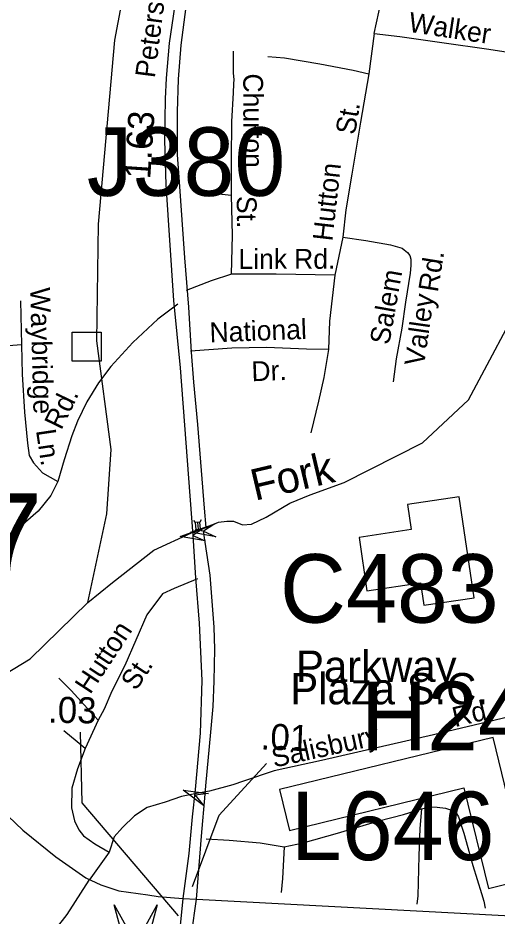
# Model space of a CAD drawing. Extents: x 1547597 to 1699558, y 810033 to 920809.
# Drawn here: x 1627311 to 1629607, y 845229 to 849529 of the extents above; entities that cross this region are included whole.
import ezdxf

# ---------------------------------------------------------------- set-up
doc = ezdxf.new("R2010")
doc.units = 0
for name, color, linetype in [('Exist Cultural Shopping Center Building Footprint', 7, 'Continuous'), ('Exist Cultural Shopping Center Building Label', 7, 'Continuous'), ('Exist Hydrographic Creek Single Shore', 7, 'Continuous'), ('Exist Hydrographic Creek Single Shore Label', 7, 'Continuous'), ('Exist Road Non-System Structure Non-Sys Other CELL', 7, 'Continuous'), ('Exist Road Non-System Structure Non-Sys Other Number Label', 7, 'Continuous'), ('Exist Road Non-System Type 51', 7, 'Continuous'), ('Exist Road Non-System Type 51 Label', 7, 'Continuous'), ('Exist Road Primary Interstate Structure Cantilever Sign Number Label', 7, 'Continuous'), ('Exist Road Primary Interstate Structure Standard Bridge CELL', 7, 'Continuous'), ('Exist Road Primary NC Service Mileage Hundredths English Label', 7, 'Continuous'), ('Exist Road Primary NC UnDivided 4 Lane Attributed', 7, 'Continuous'), ('Exist Road Primary US Structure Non-Sys NCDOT Attributed CELL', 7, 'Continuous'), ('Exist Road Primary US Structure Non-Sys NCDOT Number Label', 7, 'Continuous'), ('Exist Road Secondary Structure Culvert Attributed CELL', 7, 'Continuous'), ('Exist Road Secondary Structure Culvert Number Label', 7, 'Continuous'), ('Exist Road Secondary Structure Standard Bridge Attributed CELL', 7, 'Continuous'), ('Exist Road Secondary Structure Standard Bridge Number Label', 7, 'Continuous'), ('Exist Road Secondary Type 51 Undivided 4 Lane Attributed', 7, 'Continuous')]:
    doc.layers.add(name, color=color, linetype=linetype)

msp = doc.modelspace()

# ---------------------------------------------------------------- linework, layer by layer
at = {"layer": 'Exist Cultural Shopping Center Building Footprint'}
for points in [[(1629497.8, 846753.5), (1629426.1, 847236.8), (1629178.5, 847200.1), (1629196.4, 847079.4), (1628945.9, 847042.3), (1628983.8, 846786.6), (1629241.3, 846824.8), (1629257.2, 846717.8)], [(1629588.2, 846084.1), (1628565.6, 845834.9), (1628613.3, 845639.1), (1629448.5, 845842.7), (1629565.9, 845361.1), (1629753.3, 845406.8)]]:
    msp.add_lwpolyline(points, close=True, dxfattribs=at)
at = {"layer": 'Exist Hydrographic Creek Single Shore'}
for points in [[(1627645.6, 846730.9), (1627737.8, 847155.4), (1627757.8, 847463.5), (1627689.8, 847983.6), (1627697.8, 848541.5), (1627775.8, 849423), (1627945.8, 850322.2)], [(1627645.6, 846730.9), (1627765.1, 846826.2), (1627962.3, 846981.9), (1628143.4, 847063.5), (1628213.2, 847090.1), (1628273, 847114.5), (1628312.9, 847120.6), (1628344.5, 847119.5), (1628388.2, 847102.3), (1628430.9, 847106.2), (1628500.6, 847139.4), (1628614.7, 847207), (1628711.1, 847245.7), (1628875.3, 847305.9), (1629250.8, 847495.6), (1629469.9, 847701.3), (1629752.8, 848230.6), (1629887.9, 848362.4), (1630139.9, 848498.5), (1630507.4, 848857.5), (1630701.1, 849097)], [(1626579.8, 845980.8), (1626862.2, 846153.4), (1626909, 846181.6), (1627369.8, 846460.4), (1627645.6, 846730.9)]]:
    msp.add_lwpolyline(points, dxfattribs=at)
at = {"layer": 'Exist Road Non-System Structure Non-Sys Other CELL'}
msp.add_lwpolyline([(1627571.9, 848025.2), (1627710.9, 848025.2), (1627710.9, 847886.1), (1627571.9, 847886.1)], close=True, dxfattribs=at)
at = {"layer": 'Exist Road Non-System Type 51'}
for p, q in [((1629019, 849455.1), (1628992.3, 849261.9)), ((1628334.3, 848678.5), (1628257.6, 848687.6)), ((1628868, 848479.4), (1628830.3, 848298)), ((1627323.1, 848174.2), (1627327.9, 847964.2)), ((1627696.1, 846167.7), (1627632.7, 846031.3)), ((1627748.4, 845535.3), (1627652.5, 845401.8))]:
    msp.add_line(p, q, dxfattribs=at)
for points in [[(1629019, 849455.1), (1629051.7, 849608.8), (1629069.3, 849744.8), (1629094.5, 849933.8), (1629122.1, 850149.2), (1629144.7, 850300.3), (1629174.9, 850373.4), (1629227.8, 850489.3), (1629343.6, 850781.6), (1629449.5, 851019.3)], [(1629019, 849455.1), (1629140.9, 849440.6), (1629342.2, 849411.7), (1629567.8, 849379.5), (1629784.3, 849346.7), (1629906, 849323.1), (1629962.1, 849316.8), (1630000.9, 849311.4), (1630067.5, 849334), (1630162.6, 849414.5)], [(1628334.3, 848678.5), (1628334.3, 848852.3), (1628336.8, 849033.8), (1628344.9, 849170.1), (1628345.3, 849213.2), (1628347.1, 849234.7), (1628344.4, 849264.6), (1628343.6, 849370.9)], [(1628508.4, 849344.5), (1628588.7, 849337.8), (1628758.9, 849310.2), (1628918.3, 849280.1), (1628992.3, 849261.9)], [(1628992.3, 849261.9), (1628953.6, 849030.3), (1628910.8, 848780.9), (1628883.1, 848610.5), (1628868, 848479.4)], [(1628334.3, 848303.1), (1628339.3, 848489.5), (1628334.3, 848678.5)], [(1628868, 848479.4), (1628978.8, 848464.3), (1629097.2, 848442.9), (1629152.6, 848427.8), (1629163.1, 848418.4), (1629177.6, 848406.9), (1629189.3, 848392.3), (1629193.8, 848373.8), (1629194.8, 848343.8), (1629190.8, 848307.8), (1629168.6, 848168.4), (1629150.9, 848044.7), (1629124.5, 847897.1), (1629108.8, 847787.6)], [(1628334.3, 848303.1), (1628237.2, 848270.1), (1628117.2, 848223.9)], [(1628830.3, 848298), (1628548.3, 848303.1), (1628334.3, 848303.1)], [(1628830.3, 848298), (1628805.2, 848077.5), (1628799.6, 847942)], [(1628077.1, 848159.6), (1627981.1, 848086.4), (1627861.6, 847976.2), (1627755.8, 847859.9), (1627696.8, 847782.8), (1627641.3, 847691.7), (1627596, 847598.4), (1627569, 847528.9), (1627533.2, 847413.5), (1627501.7, 847310.1)], [(1627327.9, 847964.2), (1627181.8, 847952.4), (1627045.9, 847954.5)], [(1627327.9, 847964.2), (1627331.6, 847824.3), (1627342.9, 847642.1), (1627356.8, 847494.2), (1627365.7, 847433.9), (1627385.3, 847399.7), (1627428.5, 847351), (1627501.7, 847310.1)], [(1628799.6, 847942), (1628693.8, 847943.7), (1628503.1, 847951.6), (1628336.9, 847949.1), (1628138, 847933.9)], [(1628799.6, 847942), (1628777.5, 847808), (1628752.3, 847694.6), (1628714.5, 847543.4)], [(1627501.7, 847310.1), (1627468.7, 847242.5), (1627407.6, 847167.5), (1627310.4, 847083.1), (1627189.4, 847006.9), (1627018.3, 846917.5), (1626853.3, 846842), (1626774.9, 846817.2), (1626696.5, 846790.4), (1626620.3, 846773.5), (1626533, 846759.7), (1626404, 846746.9)], [(1628172.2, 846844.6), (1628060.6, 846798.3), (1628004.2, 846772.5), (1627928.9, 846671.3), (1627823.1, 846428.9), (1627762, 846306.6), (1627724.4, 846219.5), (1627696.1, 846167.7)], [(1627507.4, 846368.5), (1627566.4, 846309.6), (1627660.8, 846206.3), (1627696.1, 846167.7)], [(1629997.5, 846262.9), (1629942, 846253.7), (1629857.6, 846229.4), (1629632.2, 846175), (1629302.1, 846096.3), (1629037.5, 846036.2), (1628766.2, 845974.6), (1628539.7, 845923.9), (1628392.4, 845874.8), (1628341.5, 845857.5), (1628228.9, 845826.6), (1628166.9, 845815.5), (1628095.4, 845801.3), (1628017.4, 845775.3), (1627930.5, 845749.8), (1627870, 845708.6), (1627811.9, 845652.9), (1627772.9, 845608.7), (1627748.4, 845535.3)], [(1627632.7, 846031.3), (1627594.7, 846063.3), (1627531.5, 846116.2)], [(1627632.7, 846031.3), (1627597.4, 845934.8), (1627570, 845841.5), (1627567.4, 845747.7), (1627583, 845685.8), (1627603.4, 845642.3), (1627625.8, 845613.3), (1627679.2, 845574.4), (1627748.4, 845535.3)], [(1629245.7, 845742.9), (1629285.7, 845752.3), (1629320.1, 845751), (1629360.4, 845746.2), (1629393.4, 845734.7), (1629404.2, 845728.1), (1629413.1, 845720.5), (1629422.8, 845703.7), (1629447.6, 845625.9), (1629491.1, 845471.4), (1629533, 845336.8), (1629544.5, 845300.8), (1629550.3, 845267.6)], [(1628587.4, 845560.9), (1628677.6, 845579.5), (1628842.3, 845627), (1629041, 845686), (1629159.3, 845716.2), (1629245.7, 845742.9)], [(1629245.7, 845742.9), (1629238.1, 845649), (1629232.1, 845517.2), (1629227.2, 845325.4), (1629223.2, 845286.5)], [(1628213, 845599.3), (1628324.3, 845592.9), (1628472, 845580.7), (1628587.4, 845560.9)], [(1628587.4, 845560.9), (1628579.1, 845409), (1628572.4, 845342.1)], [(1627442.1, 845100.9), (1627455.7, 845120.2), (1627547.3, 845236.8), (1627652.5, 845401.8)]]:
    msp.add_lwpolyline(points, dxfattribs=at)
at = {"layer": 'Exist Road Primary Interstate Structure Standard Bridge CELL'}
for p, q in [((1628190.2, 847126.5), (1628183.4, 847115.2)), ((1628152.8, 847123.5), (1628161.3, 847113.4)), ((1628172.4, 847114.3), (1628175, 847081.1)), ((1628186, 847082), (1628194.5, 847071.9)), ((1628164.2, 847080.3), (1628157.4, 847069))]:
    msp.add_line(p, q, dxfattribs=at)
msp.add_lwpolyline([(1628161.3, 847113.4), (1628164, 847080.3), (1628186, 847082), (1628183.4, 847115.2)], close=True, dxfattribs=at)
at = {"layer": 'Exist Road Primary NC Service Mileage Hundredths English Label'}
for points in [[(1628080.1, 845229.9), (1627619.1, 845772), (1627610.6, 846109.2)], [(1628148.4, 845370.8), (1628276.4, 845712.3), (1628502.7, 845959.8)]]:
    msp.add_lwpolyline(points, dxfattribs=at)
at = {"layer": 'Exist Road Primary NC UnDivided 4 Lane Attributed'}
for points in [[(1628213.2, 847090.1), (1628205.5, 847181.5), (1628173.3, 847582.8), (1628154.4, 847785.4), (1628143.6, 847928.5), (1628130.1, 848145.2), (1628111.2, 848380.1), (1628085.3, 848744.8), (1628076.4, 848873.9), (1628076.2, 849079.5), (1628080.3, 849236), (1628094.2, 849398.3), (1628135.8, 849717.6), (1628381.4, 851347.6), (1628428.5, 851658.8), (1628437.9, 852403.8), (1628398.8, 853218.1)], [(1628109.1, 849906.7), (1628036, 849408.8), (1628021.1, 849241.6), (1628016.6, 849142.4), (1628014.1, 848944.5), (1628019.9, 848731), (1628056.5, 848176.6), (1628088.6, 847853.7), (1628149.4, 847052.2)], [(1628149.4, 847052.2), (1628162.8, 846849.2), (1628180.5, 846631), (1628192.2, 846356.4), (1628184.4, 846105.5), (1628161.2, 845834.7)], [(1628211.3, 845852.2), (1628236.5, 846110.5), (1628247, 846232.9), (1628251.4, 846353.6), (1628254.2, 846507.5), (1628252.5, 846612.2), (1628232.6, 846862), (1628200.9, 847071.7)], [(1626940.5, 846115.1), (1626973.8, 846048.5), (1627067.6, 845921.8), (1627151.5, 845817.8), (1627228.7, 845740.7), (1627334.6, 845640.8), (1627493.4, 845512.2), (1627636.4, 845412.4), (1627708.7, 845379.5), (1627794.6, 845350.1), (1627934.1, 845330.2), (1627984, 845323), (1628100.8, 845313.6)], [(1628161.2, 845834.7), (1628146.8, 845704), (1628129.6, 845529), (1628100.8, 845313.6)], [(1628167.8, 845310.8), (1628191.2, 845612.5), (1628208.4, 845813.1), (1628211.3, 845852.2)], [(1628100.8, 845313.6), (1628083.6, 845136.9)], [(1628100.8, 845313.6), (1628167.8, 845310.8)], [(1628142.9, 845140.3), (1628167.8, 845310.8)]]:
    msp.add_lwpolyline(points, dxfattribs=at)
at = {"layer": 'Exist Road Primary US Structure Non-Sys NCDOT Attributed CELL'}
msp.add_lwpolyline([(1628200.8, 845758.1), (1628103.4, 845831.4), (1628224.4, 845816.6), (1628160, 845808.6)], close=True, dxfattribs=at)
at = {"layer": 'Exist Road Secondary Structure Culvert Attributed CELL'}
msp.add_lwpolyline([(1627979.3, 845283.4), (1627875.8, 844897), (1627772.3, 845283.4), (1627875.8, 845097)], close=True, dxfattribs=at)
at = {"layer": 'Exist Road Secondary Structure Standard Bridge Attributed CELL'}
for points in [[(1628208.5, 847025.3), (1628088.6, 847047.4), (1628203.5, 847088.2), (1628149.4, 847052.2)], [(1628260, 847044.8), (1628140.1, 847066.9), (1628255, 847107.7), (1628200.9, 847071.7)]]:
    msp.add_lwpolyline(points, close=True, dxfattribs=at)
at = {"layer": 'Exist Road Secondary Type 51 Undivided 4 Lane Attributed'}
msp.add_lwpolyline([(1628167.8, 845310.8), (1629643.6, 845231.6), (1630009.7, 845198.4), (1631069.9, 845128.2)], dxfattribs=at)

# ---------------------------------------------------------------- texts
at = {"layer": 'Exist Cultural Shopping Center Building Label'}
for s, p in [('Parkway', (1628644, 846350.6)), ('Plaza S.C.', (1628616.6, 846243))]:
    msp.add_text(s, height=150, dxfattribs=at).set_placement(p)
at = {"layer": 'Exist Hydrographic Creek Single Shore Label'}
msp.add_text('Fork', height=150, rotation=13.2006, dxfattribs=at).set_placement((1628447.1, 847217.3))
at = {"layer": 'Exist Road Non-System Structure Non-Sys Other Number Label'}
msp.add_text('J380', height=328.08, dxfattribs=at).set_placement((1627641.4, 848677.5))
at = {"layer": 'Exist Road Non-System Type 51 Label'}
for s, rotation, p in [('Peters', 82.6785, (1627966.9, 849239.2)), ('Walker', 351.3639, (1629179, 849463.9)), ('Churton', 270.1886, (1628390.9, 849263.5)), ('St.', 80.8189, (1628926.8, 848966.7)), ('Hutton', 83.5193, (1628817.7, 848457.8)), ('St.', 270.7496, (1628359.7, 848676.9)), ('Link', 0.1507, (1628368.2, 848327.7)), ('Rd.', 359.9684, (1628634.9, 848328.3)), ('Rd.', 80.938, (1629323.4, 848213.1)), ('Salem', 79.854, (1629090.3, 847960.8)), ('Waybridge', 271.5402, (1627369.7, 848238.1)), ('Valley', 81.8486, (1629257.2, 847858.8)), ('National', 2.1154, (1628231.3, 847975.9)), ('Dr.', 2.1154, (1628432, 847789.7)), ('Rd.', 64.101, (1627519.1, 847552.6)), ('Ln.', 278.4877, (1627397.5, 847554.4)), ('Hutton', 56.6077, (1627657.3, 846287.1)), ('St.', 56.6077, (1627877.3, 846304.2)), ('Rd.', 13.2541, (1629405.5, 846133.7)), ('Salisbury', 12.3963, (1628538.8, 845939.6))]:
    msp.add_text(s, height=95, rotation=rotation, dxfattribs=at).set_placement(p)
at = {"layer": 'Exist Road Primary Interstate Structure Cantilever Sign Number Label'}
msp.add_text('L646', height=328.08, dxfattribs=at).set_placement((1628619.3, 845497))
at = {"layer": 'Exist Road Primary NC Service Mileage Hundredths English Label'}
for s, rotation, p in [('1.63', 86.168, (1627944.9, 848755.4)), ('.03', 359.0234, (1627454.9, 846155.2)), ('.01', 357.6338, (1628472.7, 846027.6))]:
    msp.add_text(s, height=125, rotation=rotation, dxfattribs=at).set_placement(p)
at = {"layer": 'Exist Road Primary US Structure Non-Sys NCDOT Number Label'}
msp.add_text('H243', height=328.08, dxfattribs=at).set_placement((1628955, 846023.4))
at = {"layer": 'Exist Road Secondary Structure Culvert Number Label'}
msp.add_text('C483', height=328.08, dxfattribs=at).set_placement((1628566.5, 846634))
at = {"layer": 'Exist Road Secondary Structure Standard Bridge Number Label'}
msp.add_text('7', height=410.1, dxfattribs=at).set_placement((1627124.4, 846843.1))

doc.saveas('drawing.dxf')
